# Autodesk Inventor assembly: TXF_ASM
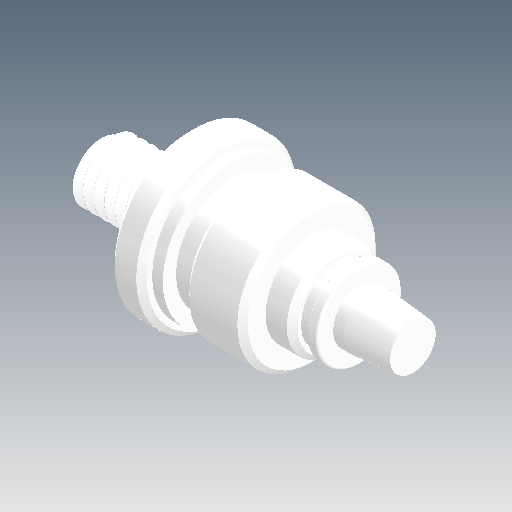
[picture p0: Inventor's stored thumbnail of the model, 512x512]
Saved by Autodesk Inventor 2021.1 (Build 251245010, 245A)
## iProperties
Created: 2021-05
Part Number: TXF_ASM
Document SubType Name: Assembly
Designer: user
Author: user
Revision Number: ÈÎºÎ
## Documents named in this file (3)
- D:\Vault_2016\Projekty\Clamptek\Hydraulic\CHLC\CHLC-50\Inventor\CHLC-MF50\TXF_ASM.iam
- D:\Vault_2016\Projekty\Clamptek\Hydraulic\CHLC\CHLC-50\Inventor\CHLC-MF50\TXF-02.ipt
- D:\Vault_2016\Projekty\Clamptek\Hydraulic\CHLC\CHLC-50\Inventor\CHLC-MF50\TSF-01.ipt
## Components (2 placed, 2 different names)
1. TXF-02_21
2. TSF-01_22
